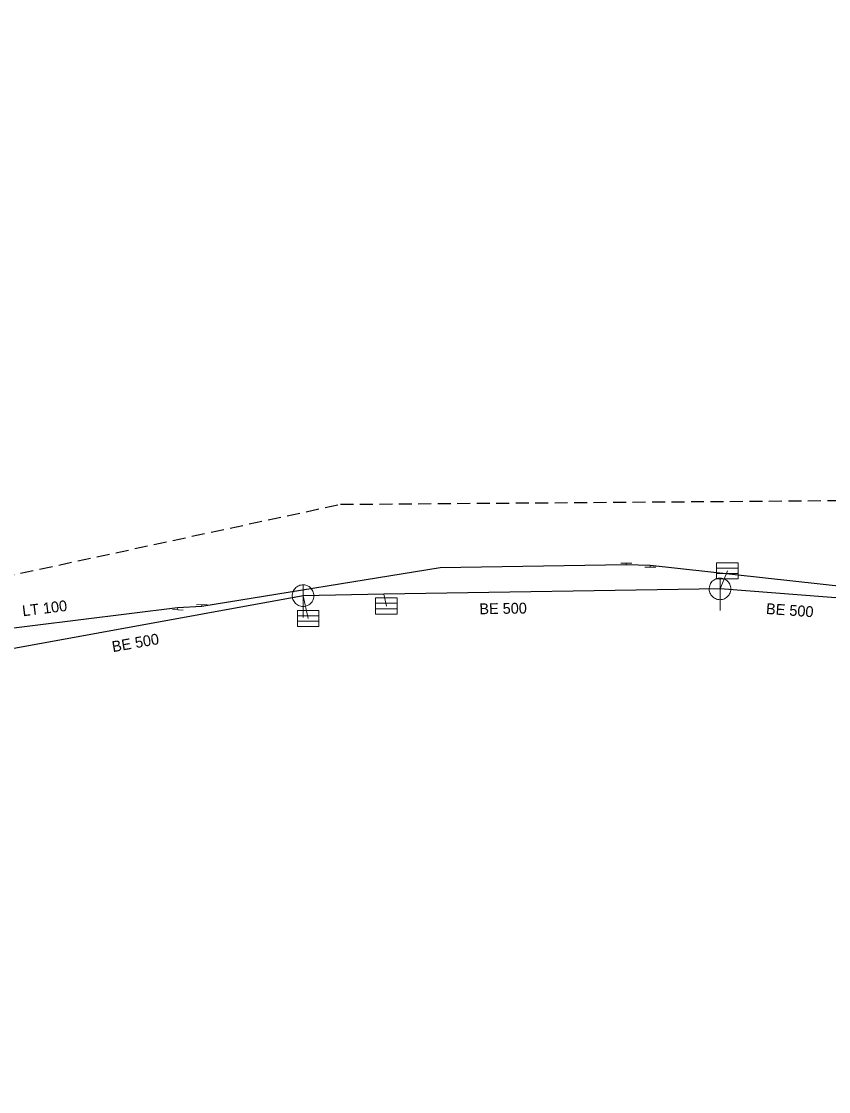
# Model space of a CAD drawing. Extents: x -687013 to -686506, y -973869 to -973672.
# Drawn here: x -686875.8 to -686801.2, y -973770.5 to -973671.6 of the extents above; entities that cross this region are included whole.
import ezdxf

# ---------------------------------------------------------------- set-up
doc = ezdxf.new("R2010")
doc.units = 0
doc.header["$LTSCALE"] = 0.4
doc.linetypes.add('MEDIUM_DASHED', pattern=[4.5, 3, -1.5])
doc.layers.add('1', color=7, linetype='Continuous')
for name, color, linetype, lineweight in [('11', 7, 'Continuous', 13), ('14', 7, 'Continuous', 25), ('17', 7, 'Continuous', 25), ('22', 7, 'Continuous', 13), ('34', 7, 'Continuous', 13), ('63', 7, 'MEDIUM_DASHED', 25)]:
    doc.layers.add(name, color=color, linetype=linetype, lineweight=lineweight)

msp = doc.modelspace()

# ---------------------------------------------------------------- linework, layer by layer
at = {"layer": '11'}
for p, q in [((-686810.51, -973722.38), (-686811.2, -973724.04)), ((-686849.25, -973726.78), (-686849.73, -973724.67)), ((-686842.02, -973725.63), (-686842.258, -973724.526))]:
    msp.add_line(p, q, dxfattribs=at)
at = {"layer": '14', "lineweight": 13}
for p, q in [((-686819.859, -973721.829), (-686819.859, -973721.669)), ((-686817.64, -973722.03), (-686817.64, -973721.882)), ((-686861.337, -973725.804), (-686861.299, -973725.979)), ((-686859.074, -973725.682), (-686859.089, -973725.5))]:
    msp.add_line(p, q, dxfattribs=at)
at = {"layer": '14'}
for p, q in [((-686849.73, -973724.67), (-686879.68, -973730.129)), ((-686796.46, -973725.17), (-686811.199, -973724.039))]:
    msp.add_line(p, q, dxfattribs=at)
msp.add_lwpolyline([(-686811.199, -973724.039), (-686842.258, -973724.526), (-686849.73, -973724.67)], dxfattribs=at)
at = {"layer": '17'}
msp.add_lwpolyline([(-686778.16, -973716.008), (-686787.234, -973721.504), (-686796.6, -973724.188), (-686817.64, -973721.881), (-686819.859, -973721.829), (-686837.05, -973722.085), (-686859.074, -973725.682), (-686861.337, -973725.804), (-686883.709, -973728.57)], dxfattribs=at)
at = {"layer": '22'}
for p, q in [((-686811.521, -973722.123), (-686809.521, -973722.123)), ((-686811.521, -973722.623), (-686809.521, -973722.623)), ((-686849.73, -973726.67), (-686849.729, -973723.67)), ((-686811.199, -973726.039), (-686811.198, -973723.039)), ((-686843.031, -973725.373), (-686841.031, -973725.373)), ((-686843.031, -973725.873), (-686841.031, -973725.873)), ((-686850.261, -973726.523), (-686848.261, -973726.523)), ((-686850.261, -973727.023), (-686848.261, -973727.023))]:
    msp.add_line(p, q, dxfattribs=at)
for points in [[(-686811.521, -973721.623), (-686809.521, -973721.623), (-686809.521, -973723.123), (-686811.521, -973723.123)], [(-686848.73, -973724.67), (-686848.735, -973724.561), (-686848.753, -973724.453), (-686848.783, -973724.347), (-686848.823, -973724.246), (-686848.875, -973724.149), (-686848.937, -973724.059), (-686849.009, -973723.976), (-686849.089, -973723.902), (-686849.177, -973723.836), (-686849.271, -973723.781), (-686849.371, -973723.736), (-686849.476, -973723.703), (-686849.583, -973723.681), (-686849.692, -973723.671), (-686849.802, -973723.673), (-686849.91, -973723.687), (-686850.017, -973723.712), (-686850.12, -973723.749), (-686850.218, -973723.798), (-686850.31, -973723.856), (-686850.396, -973723.925), (-686850.473, -973724.002), (-686850.542, -973724.088), (-686850.601, -973724.18), (-686850.649, -973724.278), (-686850.686, -973724.381), (-686850.712, -973724.488), (-686850.726, -973724.596), (-686850.729, -973724.706), (-686850.719, -973724.815), (-686850.698, -973724.922), (-686850.664, -973725.026), (-686850.62, -973725.126), (-686850.565, -973725.221), (-686850.499, -973725.309), (-686850.425, -973725.389), (-686850.342, -973725.461), (-686850.252, -973725.523), (-686850.156, -973725.575), (-686850.054, -973725.616), (-686849.949, -973725.646), (-686849.841, -973725.664), (-686849.731, -973725.67), (-686849.622, -973725.664), (-686849.514, -973725.646), (-686849.409, -973725.617), (-686849.307, -973725.576), (-686849.21, -973725.524), (-686849.12, -973725.462), (-686849.037, -973725.391), (-686848.962, -973725.311), (-686848.897, -973725.223), (-686848.841, -973725.129), (-686848.797, -973725.029), (-686848.763, -973724.925), (-686848.741, -973724.817), (-686848.731, -973724.708)], [(-686810.199, -973724.039), (-686810.204, -973723.93), (-686810.222, -973723.822), (-686810.252, -973723.716), (-686810.292, -973723.615), (-686810.344, -973723.518), (-686810.406, -973723.428), (-686810.478, -973723.345), (-686810.558, -973723.271), (-686810.646, -973723.205), (-686810.74, -973723.15), (-686810.84, -973723.105), (-686810.945, -973723.072), (-686811.052, -973723.05), (-686811.161, -973723.04), (-686811.271, -973723.042), (-686811.379, -973723.056), (-686811.486, -973723.081), (-686811.589, -973723.118), (-686811.687, -973723.167), (-686811.779, -973723.225), (-686811.865, -973723.294), (-686811.942, -973723.371), (-686812.011, -973723.457), (-686812.07, -973723.549), (-686812.118, -973723.647), (-686812.155, -973723.75), (-686812.181, -973723.857), (-686812.195, -973723.965), (-686812.198, -973724.075), (-686812.188, -973724.184), (-686812.167, -973724.291), (-686812.133, -973724.395), (-686812.089, -973724.495), (-686812.034, -973724.59), (-686811.968, -973724.678), (-686811.894, -973724.758), (-686811.811, -973724.83), (-686811.721, -973724.892), (-686811.625, -973724.944), (-686811.523, -973724.985), (-686811.418, -973725.015), (-686811.31, -973725.033), (-686811.2, -973725.039), (-686811.091, -973725.033), (-686810.983, -973725.015), (-686810.878, -973724.986), (-686810.776, -973724.945), (-686810.679, -973724.893), (-686810.589, -973724.831), (-686810.506, -973724.76), (-686810.431, -973724.68), (-686810.366, -973724.592), (-686810.31, -973724.498), (-686810.266, -973724.398), (-686810.232, -973724.294), (-686810.21, -973724.186), (-686810.2, -973724.077)], [(-686843.031, -973724.873), (-686841.031, -973724.873), (-686841.031, -973726.373), (-686843.031, -973726.373)], [(-686850.261, -973726.023), (-686848.261, -973726.023), (-686848.261, -973727.523), (-686850.261, -973727.523)]]:
    msp.add_lwpolyline(points, close=True, dxfattribs=at)
at = {"layer": '34'}
for p, q in [((-686819.359, -973721.665), (-686820.358, -973721.671)), ((-686818.14, -973722.03), (-686817.14, -973722.03)), ((-686858.589, -973725.475), (-686859.588, -973725.523)), ((-686861.798, -973725.955), (-686860.799, -973726.003))]:
    msp.add_line(p, q, dxfattribs=at)
at = {"layer": '63'}
msp.add_lwpolyline([(-686909.784, -973869.363), (-686968.065, -973779.329), (-686968.065, -973779.329), (-686933.901, -973735.117), (-686933.901, -973735.117), (-686846.279, -973716.226), (-686846.279, -973716.226), (-686793.223, -973715.824), (-686793.223, -973715.824), (-686767.901, -973696.129), (-686767.901, -973696.129), (-686632.047, -973671.611), (-686632.047, -973671.611), (-686619.587, -973774.908), (-686619.587, -973774.908), (-686749.412, -973818.317), (-686749.412, -973818.317)], close=True, dxfattribs=at)

# ---------------------------------------------------------------- texts
at = {"layer": '1'}
for s, rotation, p in [('LT 100', 7, (-686875.62, -973726.576)), ('BE 500', 1, (-686833.431, -973726.388)), ('BE 500', 356, (-686806.972, -973726.354)), ('BE 500', 10, (-686867.299, -973729.89))]:
    msp.add_text(s, height=1, rotation=rotation, dxfattribs=at).set_placement(p)

doc.saveas('drawing.dxf')
